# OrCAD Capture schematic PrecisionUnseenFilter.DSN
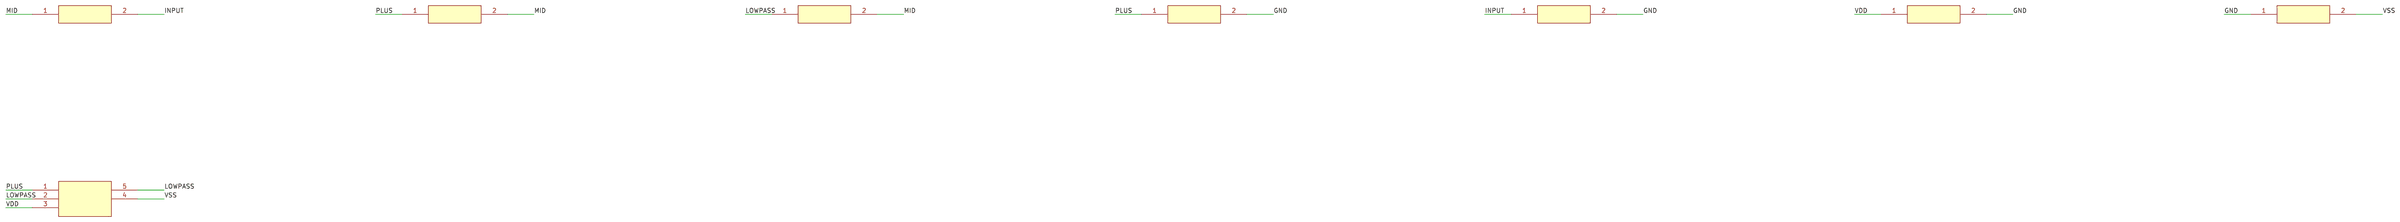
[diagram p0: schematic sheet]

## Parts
C1  100n
C2  100n
R1  1k
R2  1k
U1  AD8051
V1  ac=1
V2  10
V3  10

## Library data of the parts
C1 = OBS_C1
C2 = OBS_C2
R1 = OBS_R1
R2 = OBS_R2
U1 = OBS_U1
V1 = OBS_V1
V2 = OBS_V2
V3 = OBS_V3

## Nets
GND: C2.2 V1.2 V2.2 V3.1
VDD: U1.3 V2.1
VSS: U1.4 V3.2
INPUT: R1.2 V1.1
LOWPASS: C1.1 U1.2 U1.5
MID: C1.2 R1.1 R2.2
PLUS: C2.1 R2.1 U1.1
